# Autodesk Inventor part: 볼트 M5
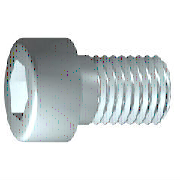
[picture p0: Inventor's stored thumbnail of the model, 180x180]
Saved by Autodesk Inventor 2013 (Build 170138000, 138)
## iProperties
IsCustomPart: 0
Created: 2021-07
Part Number: 볼트 M5
Material: 강철, 연강
Description: 6각머리 태핑 나사
Document SubType Name: Modeling
Standard: KS B 1003
Standards Organization: KS
Language: ko-KR
Size Designation: M 5 x 20
Categories: <MemberInstance><Categories><Category DisplayName="조임쇠" InternalName="e4da775c-781d-43d5-af7c-5136215cf5a6" Mnemonic="FSTN"><Category DisplayName="볼트" InternalN
Density: 7.86 g/cm^3
Mass: 4.9629 g
Surface Area: 5.88237 cm^2
Volume: 0.631412 cm^3
Project: mdu
Author: mdu
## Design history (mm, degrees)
sketch "스케치1"
  geometry: L1 (-1.167, 0)-(20, 0); L2 (20, 0)-(20, 2.5); L3 (20, 2.5)-(2, 2.5); L4 (2, 2.5)-(1.509, 2.5); L5 (1.509, 2.5)-(0, 2.5); L6 (0, 2.5)-(0, 4.25); L7 (0, 4.25)-(-5, 4.25); L8 (-5, 4.25)-(-5, 2.309); L9 (-5, 2.309)-(-2.5, 2.309); L10 (-2.5, 2.309)-(-1.167, 0); L11 (-10, 0)-(25, 0) reference; L12 (0, -0.85)-(0, 5.1) reference; L13 (2, 2.5)-(0, 2.5)
  constraints: 22 end point, 6 parallel, 2 collinear, 2 perpendicular, 1 horizontal, 1 point on line
  dimensions: "d1" = 18 distance from line of L3.end L2 (= GEL); "d2" = 0.49086 distance of L4.end L3.end (computed from GAL); "d3" = 5 distance between parallel lines of L8 L6 (= KOH); "d4" = 2.5 distance of L8.end L9.end (= INTI); "d5" = 60 deg angle of L10 L1; "d6" = 5 diameter of L3 L1 (= GD); "d7" = 5 diameter of L5 L1 (= BDM); "d8" = 4.6188 diameter of L9 L1 (= 1.1547 x SW); "d9" = 8.5 diameter of L7 L1 (= KOD); "d26" = 20 distance between parallel lines of L12 L2 (= NLG)
revolve "본체" sketch "스케치1" stored, may be unused: angle "d10" = 90 deg
sketch "스케치2"
  geometry: L1 (0, -5.95)-(0, 5.95) reference; L2 (-5.95, 0)-(5.95, 0) reference; L3 (2.309, 0)-(1.155, -2); L4 (1.155, -2)-(-1.155, -2); L5 (-1.155, -2)-(-2.309, 0); L6 (-2.309, 0)-(-1.155, 2); L7 (-1.155, 2)-(1.155, 2); L8 (1.155, 2)-(2.309, 0); 2 further points
  constraints: 12 end point, 1 coincident, 1 horizontal alignment, 1 point on line, 12 other
extrude "슬롯" join sketch "스케치2" stored distance "d11" = 10; taper "d12" = 0 deg
workplane "Work Plane1"
fillet "Fillet2" dims "d30" = 0.1 (= R)
body "Solid1"
fillet "모깎기1" dims "d17" = 0.5 (= RR)
feature "스레드" dims "d13" = 18 (= GEL), "d14" = 0
chamfer "모따기1" distance "d15" = 0.49076 (= -0.5 x SPD + 0.5 x GD); stored, may be unused: second distance "d16" = 0.49076 (= GUL), angle "d27" = 45 deg
other parameters: "GD" = 5 (= NND) [user parameter; used in 2 equation terms], "NLG" = 20 [user parameter; used in 1 equation term], "GEL" = 18 [user parameter; used in 2 equation terms], "KOD" = 8.5 [user parameter; used in 1 equation term], "KOH" = 5 [user parameter; used in 1 equation term], "INTI" = 2.5 [user parameter; used in 1 equation term], "GAL" = 0.49076 (= 0.61345 x PTC) [user parameter; used in 1 equation term], "GUL" = 0.49076 (= 0.61345 x PTC) [user parameter; used in 1 equation term], "BDM" = 5 (= NND) [user parameter; used in 1 equation term], "SW" = 4 [user parameter; used in 2 equation terms], "RR" = 0.5 [user parameter; used in 1 equation term], "SPD" = 4.01848 (= NND - 1.2269 x PTC) [user parameter; used in 1 equation term], "d19" = 0, "d28" = 0, "d29" = 0, "R" = 0.1 [user parameter; used in 1 equation term], "PHH" = 0.2 [user parameter], "GD1" = 4.01848 (= THREADDIA - 1.2269 x PTC) [user parameter], "THREADDIA" = 5 [user parameter; used in 1 equation term], "FAWI" = 45 deg [user parameter], "TPU" = 12.5 (computed from PTC) [user parameter], "PTC" = 0.8 [user parameter; used in 5 equation terms], "NND" = 5 [user parameter; used in 3 equation terms], "TOA" = 30 deg [user parameter], "E0" = 4.62 (= 1.155 x SW) [user parameter]
